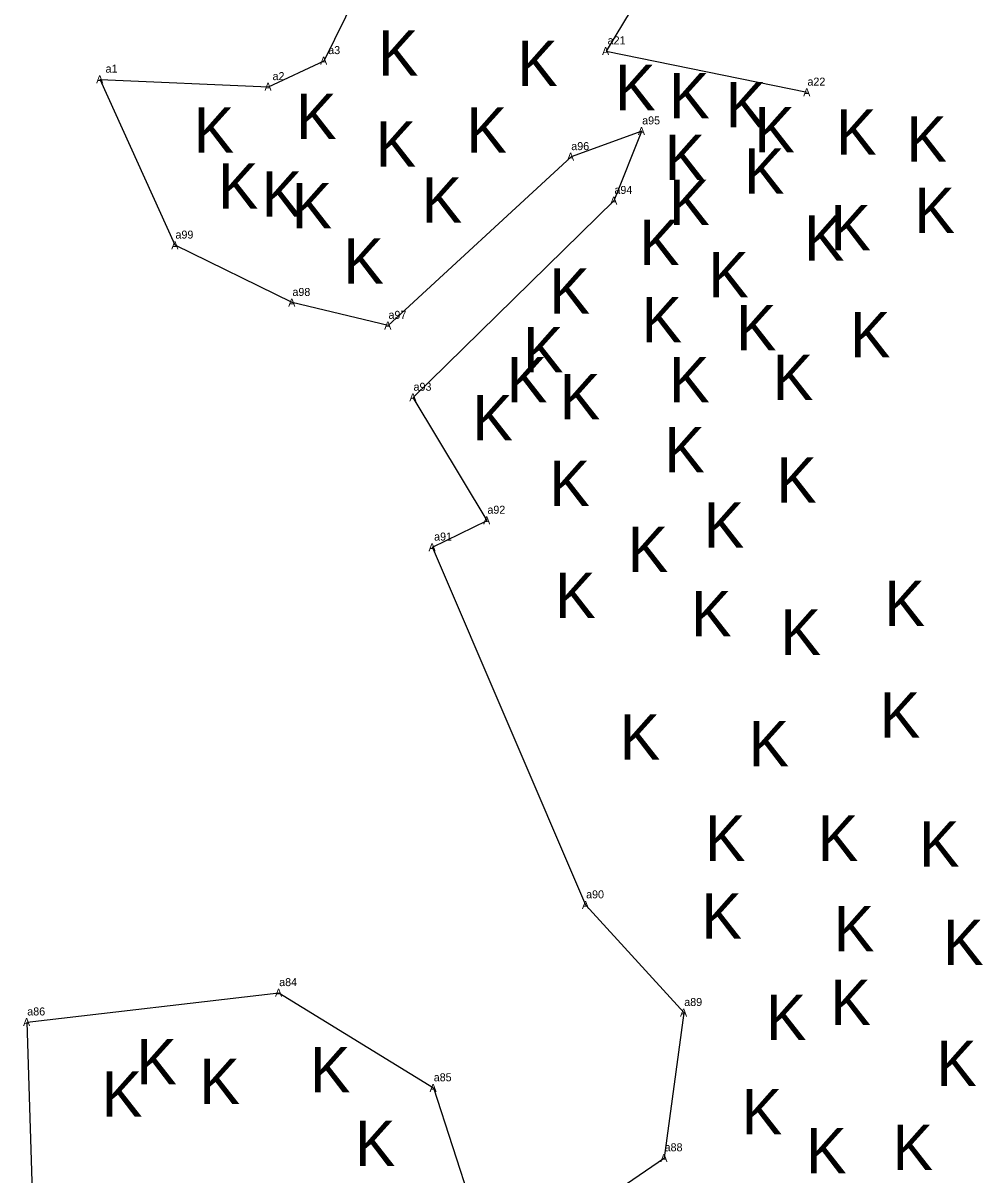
# Model space of a CAD drawing. Extents: x 2028512 to 2029541, y 737100 to 738747.
# Drawn here: x 2028876.1 to 2029056, y 738021.9 to 738237.8 of the extents above; entities that cross this region are included whole.
import ezdxf

# ---------------------------------------------------------------- set-up
doc = ezdxf.new("R2010")
doc.units = 0
for name, color, linetype in [('Old_Level_10', 7, 'Continuous'), ('Old_Level_20', 7, 'Continuous'), ('Old_Level_52', 7, 'Continuous'), ('Old_Level_61', 7, 'Continuous')]:
    doc.layers.add(name, color=color, linetype=linetype)

msp = doc.modelspace()

# ---------------------------------------------------------------- linework, layer by layer
at = {"layer": 'Old_Level_52'}
for points in [[(2028904.65, 738196.15), (2028890.57, 738227.25), (2028922.11, 738225.85), (2028932.53, 738230.73), (2028946.73, 738259.58), (2028951.13, 738263.7), (2028950.51, 738268.13), (2028918.78, 738305.31), (2028920.65, 738342.72), (2028937.45, 738359.38), (2028945.21, 738340.29), (2028965.8, 738354.45), (2028965.12, 738369.93), (2028963.42, 738385.89), (2028937.56, 738400.24), (2028943.82, 738411.81), (2028965.6, 738422.83), (2028991.98, 738397.81)], [(2028991.98, 738397.81), (2029011.35, 738375.11), (2028997.67, 738337.71), (2028951.19, 738296.51), (2028985.14, 738248.66), (2028998.01, 738253.46), (2028985.36, 738232.55), (2029023.05, 738224.82)], [(2028949.25, 738167.62), (2028986.88, 738204.52), (2028992.08, 738217.55), (2028978.8, 738212.73), (2028944.55, 738181.11), (2028926.56, 738185.4), (2028904.65, 738196.15)], [(2028878.7, 737992.71), (2028876.87, 738050.54), (2028924.08, 738056.04), (2028953.04, 738038.2), (2028963.71, 738005.21), (2028969.41, 738006.68), (2028996.29, 738025.08), (2028999.97, 738052.31), (2028981.59, 738072.49), (2028952.85, 738139.55), (2028963.08, 738144.58), (2028949.25, 738167.62)]]:
    msp.add_lwpolyline(points, dxfattribs=at)

# ---------------------------------------------------------------- texts
at = {"layer": 'Old_Level_10'}
for p in [(2028942.61, 738227.94), (2028968.72, 738226), (2028987.05, 738221.47), (2028997.19, 738219.96), (2029007.76, 738218.23), (2028927.3, 738216.07), (2028908.1, 738213.48), (2028959.22, 738213.48), (2029013.15, 738213.57), (2029028.47, 738213.14), (2029041.63, 738211.84), (2028942.18, 738210.89), (2028996.33, 738208.39), (2029011.21, 738205.8), (2028912.63, 738202.99), (2028920.83, 738201.48), (2028950.81, 738200.4), (2028926.44, 738199.32), (2028997.19, 738199.97), (2029043.14, 738198.46), (2029027.39, 738195.22), (2028991.58, 738192.42), (2029022.43, 738193.28), (2028936.14, 738188.96), (2029004.52, 738186.37), (2028974.76, 738183.35), (2028992.01, 738177.96), (2029009.7, 738176.45), (2029031.06, 738175.15), (2028969.79, 738172.34), (2028966.77, 738166.73), (2028997.19, 738166.73), (2029016.6, 738167.17), (2028976.7, 738163.5), (2028960.3, 738159.61), (2028996.27, 738153.59), (2028974.76, 738147.25), (2029017.25, 738147.89), (2029003.66, 738139.48), (2028989.42, 738134.93), (2028975.83, 738126.31), (2029037.53, 738124.8), (2029001.29, 738122.86), (2029018.03, 738119.38), (2029036.66, 738103.86), (2028987.91, 738099.76), (2029012.07, 738098.47), (2029003.88, 738080.77), (2029025.02, 738080.77), (2029044, 738079.69), (2029003.23, 738066.2), (2029028.04, 738063.83), (2029048.53, 738061.24), (2029027.39, 738050.02), (2029015.31, 738047.21), (2028897.36, 738038.88), (2029047.23, 738038.58), (2028929.89, 738037.37), (2028909.18, 738035.21), (2028890.89, 738032.84), (2029010.78, 738029.51), (2028938.3, 738023.56), (2029022.86, 738022.18), (2029039.04, 738022.82)]:
    msp.add_text('K', height=8.5, dxfattribs=at).set_placement(p)
at = {"layer": 'Old_Level_20'}
for p in [(2028984.61, 738231.8), (2028984.61, 738231.8), (2028984.61, 738231.8), (2028984.61, 738231.8), (2028931.78, 738229.98), (2028931.78, 738229.98), (2028931.78, 738229.98), (2028931.78, 738229.98), (2028889.82, 738226.5), (2028889.82, 738226.5), (2028889.82, 738226.5), (2028889.82, 738226.5), (2028921.36, 738225.1), (2028921.36, 738225.1), (2028921.36, 738225.1), (2028921.36, 738225.1), (2029022.3, 738224.07), (2029022.3, 738224.07), (2029022.3, 738224.07), (2029022.3, 738224.07), (2028991.33, 738216.8), (2028991.33, 738216.8), (2028991.33, 738216.8), (2028991.33, 738216.8), (2028978.05, 738211.98), (2028978.05, 738211.98), (2028978.05, 738211.98), (2028978.05, 738211.98), (2028986.13, 738203.77), (2028986.13, 738203.77), (2028986.13, 738203.77), (2028986.13, 738203.77), (2028903.9, 738195.4), (2028903.9, 738195.4), (2028903.9, 738195.4), (2028903.9, 738195.4), (2028925.81, 738184.65), (2028925.81, 738184.65), (2028925.81, 738184.65), (2028925.81, 738184.65), (2028943.8, 738180.36), (2028943.8, 738180.36), (2028943.8, 738180.36), (2028943.8, 738180.36), (2028948.5, 738166.88), (2028948.5, 738166.88), (2028948.5, 738166.88), (2028948.5, 738166.88), (2028962.33, 738143.83), (2028962.33, 738143.83), (2028962.33, 738143.83), (2028962.33, 738143.83), (2028952.1, 738138.8), (2028952.1, 738138.8), (2028952.1, 738138.8), (2028952.1, 738138.8), (2028980.84, 738071.74), (2028980.84, 738071.74), (2028980.84, 738071.74), (2028980.84, 738071.74), (2028923.33, 738055.29), (2028923.33, 738055.29), (2028923.33, 738055.29), (2028923.33, 738055.29), (2028876.12, 738049.79), (2028999.22, 738051.56), (2028999.22, 738051.56), (2028999.22, 738051.56), (2028999.22, 738051.56), (2028952.29, 738037.45), (2028952.29, 738037.45), (2028952.29, 738037.45), (2028952.29, 738037.45), (2028995.54, 738024.33), (2028995.54, 738024.33), (2028995.54, 738024.33), (2028995.54, 738024.33)]:
    msp.add_text('A', height=1.5, dxfattribs=at).set_placement(p)
at = {"layer": 'Old_Level_61'}
for s, p in [('a21', (2028985.66, 738233.8)), ('a21', (2028985.66, 738233.8)), ('a21', (2028985.66, 738233.8)), ('a21', (2028985.66, 738233.8)), ('a3', (2028933.31, 738231.98)), ('a3', (2028933.31, 738231.98)), ('a3', (2028933.31, 738231.98)), ('a3', (2028933.31, 738231.98)), ('a1', (2028891.6, 738228.5)), ('a1', (2028891.6, 738228.5)), ('a1', (2028891.6, 738228.5)), ('a1', (2028891.6, 738228.5)), ('a2', (2028922.88, 738227.1)), ('a2', (2028922.88, 738227.1)), ('a2', (2028922.88, 738227.1)), ('a2', (2028922.88, 738227.1)), ('a22', (2029023.1, 738226.07)), ('a22', (2029023.1, 738226.07)), ('a22', (2029023.1, 738226.07)), ('a22', (2029023.1, 738226.07)), ('a95', (2028992.13, 738218.8)), ('a95', (2028992.13, 738218.8)), ('a95', (2028992.13, 738218.8)), ('a95', (2028992.13, 738218.8)), ('a96', (2028978.85, 738213.98)), ('a96', (2028978.85, 738213.98)), ('a96', (2028978.85, 738213.98)), ('a96', (2028978.85, 738213.98)), ('a94', (2028986.93, 738205.77)), ('a94', (2028986.93, 738205.77)), ('a94', (2028986.93, 738205.77)), ('a94', (2028986.93, 738205.77)), ('a99', (2028904.69, 738197.4)), ('a99', (2028904.69, 738197.4)), ('a99', (2028904.69, 738197.4)), ('a99', (2028904.69, 738197.4)), ('a98', (2028926.6, 738186.65)), ('a98', (2028926.6, 738186.65)), ('a98', (2028926.6, 738186.65)), ('a98', (2028926.6, 738186.65)), ('a97', (2028944.6, 738182.36)), ('a97', (2028944.6, 738182.36)), ('a97', (2028944.6, 738182.36)), ('a97', (2028944.6, 738182.36)), ('a93', (2028949.3, 738168.88)), ('a93', (2028949.3, 738168.88)), ('a93', (2028949.3, 738168.88)), ('a93', (2028949.3, 738168.88)), ('a92', (2028963.13, 738145.83)), ('a92', (2028963.13, 738145.83)), ('a92', (2028963.13, 738145.83)), ('a92', (2028963.13, 738145.83)), ('a91', (2028953.15, 738140.8)), ('a91', (2028953.15, 738140.8)), ('a91', (2028953.15, 738140.8)), ('a91', (2028953.15, 738140.8)), ('a90', (2028981.63, 738073.74)), ('a90', (2028981.63, 738073.74)), ('a90', (2028981.63, 738073.74)), ('a90', (2028981.63, 738073.74)), ('a84', (2028924.12, 738057.29)), ('a84', (2028924.12, 738057.29)), ('a84', (2028924.12, 738057.29)), ('a84', (2028924.12, 738057.29)), ('a89', (2029000.02, 738053.56)), ('a89', (2029000.02, 738053.56)), ('a89', (2029000.02, 738053.56)), ('a89', (2029000.02, 738053.56)), ('a86', (2028876.92, 738051.79)), ('a85', (2028953.08, 738039.45)), ('a85', (2028953.08, 738039.45)), ('a85', (2028953.08, 738039.45)), ('a85', (2028953.08, 738039.45)), ('a88', (2028996.34, 738026.33)), ('a88', (2028996.34, 738026.33)), ('a88', (2028996.34, 738026.33)), ('a88', (2028996.34, 738026.33))]:
    msp.add_text(s, height=1.5, dxfattribs=at).set_placement(p)

doc.saveas('drawing.dxf')
